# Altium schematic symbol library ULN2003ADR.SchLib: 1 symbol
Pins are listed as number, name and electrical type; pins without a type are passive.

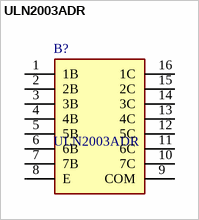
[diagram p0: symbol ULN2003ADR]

## ULN2003ADR
designator B?
Trans Darlington NPN 50V 0.5A SOIC16 Texas Instruments ULN2003ADR, 7-element NPN Darlington Transistor Array, 0.5 A 50 V, 16-Pin SOIC; Geometry.Height: 1.75mm
footprint SOIC127P600X175-16M
pins: 1 1B, 2 2B, 3 3B, 4 4B, 5 5B, 6 6B, 7 7B, 8 E, 9 COM, 10 7C, 11 6C, 12 5C, 13 4C, 14 3C, 15 2C, 16 1C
